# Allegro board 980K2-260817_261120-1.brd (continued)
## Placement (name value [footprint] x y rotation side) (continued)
NOREF#1107  -  []  201.84 295.2 0 top
NOREF#1108  -  []  88.14 151.13 90 top
NOREF#1109  -  []  194.33 267.37 90 top
NOREF#1110  -  []  237.18 236.17 90 top
NOREF#1111  -  []  243.97 210.55 90 top
NOREF#1112  -  []  204.95 264.23 90 top
NOREF#1113  -  []  230.6 233.69 90 top
NOREF#1114  -  []  281.75 206.13 0 top
NOREF#1115  -  []  186.16 253.35 0 top
NOREF#1116  -  []  214.09 207.27 90 top
NOREF#1117  -  []  283.84 200.97 90 top
NOREF#1118  -  []  266.83 251.93 0 top
NOREF#1119  -  []  275.92 255.7 90 top
NOREF#1120  -  []  276.81 172.54 0 top
NOREF#1121  -  []  236.81 172.54 0 top
NOREF#1122  -  []  149.84 213.7 0 top
NOREF#1123  -  []  196.7 257.85 90 top
NOREF#1124  -  []  152.25 282.59 0 top
NOREF#1125  -  []  242.57 231.95 0 top
NOREF#1126  -  []  233.56 233.37 90 top
NOREF#1127  -  []  262.81 186.81 0 top
NOREF#1128  -  []  187.99 238.35 0 top
NOREF#1129  -  []  147.43 224.11 0 top
NOREF#1130  -  []  265.61 197.6 0 top
NOREF#1131  -  []  149.72 221.62 0 top
NOREF#1132  -  []  228.95 266.89 0 top
NOREF#1133  -  []  168.42 265.58 0 top
NOREF#1134  -  []  142.03 289.03 90 top
NOREF#1135  -  []  262.87 273.02 0 top
NOREF#1136  -  []  187.3 286.19 0 top
NOREF#1137  -  []  168.42 205.58 0 top
NOREF#1138  -  []  279.22 239.57 90 top
NOREF#1139  -  []  119.48 456.29 0 top
NOREF#1140  -  []  188.81 195.7 90 top
NOREF#1141  -  []  241.75 266.13 0 top
NOREF#1142  -  []  89.74 155.92 90 top
NOREF#1143  -  []  233.98 238.07 0 top
NOREF#1144  -  []  277.74 226.35 90 top
NOREF#1145  -  []  248.54 260.64 90 top
NOREF#1146  -  []  166.32 214.76 0 top
NOREF#1147  -  []  176.98 265.11 90 top
NOREF#1148  -  []  199.4 202.09 0 top
NOREF#1149  -  []  222.6 82.65 0 top
NOREF#1150  -  []  211.05 185.49 90 top
NOREF#1151  -  []  141.55 205.11 90 top
NOREF#1152  -  []  239.27 265.58 0 top
NOREF#1153  -  []  237.5 185.31 90 top
NOREF#1154  -  []  149.78 228.3 0 top
NOREF#1155  -  []  187.8 209.99 0 top
NOREF#1156  -  []  149.24 185.31 90 top
NOREF#1157  -  []  243.84 208.62 0 top
NOREF#1158  -  []  283.97 270.55 90 top
NOREF#1159  -  []  156.45 247.71 0 top
NOREF#1160  -  []  187.9 265.84 90 top
NOREF#1161  -  []  133.78 207.01 0 top
NOREF#1162  -  []  272.25 212.18 90 top
NOREF#1163  -  []  270.41 168.7 90 top
NOREF#1164  -  []  279.4 272 0 top
NOREF#1165  -  []  283.84 214.21 0 top
NOREF#1166  -  []  149.56 259.27 90 top
NOREF#1167  -  []  228.99 240.62 0 top
NOREF#1168  -  []  230.77 219.22 90 top
NOREF#1169  -  []  149.84 224.11 90 top
NOREF#1170  -  []  129.05 292.28 0 top
NOREF#1171  -  []  241.75 214.76 0 top
NOREF#1172  -  []  239.65 212.56 0 top
NOREF#1173  -  []  215.65 184.35 0 top
NOREF#1174  -  []  248.54 205.9 0 top
NOREF#1175  -  []  266.96 196.43 90 top
NOREF#1176  -  []  258.95 204.09 0 top
NOREF#1177  -  []  156.57 245.63 90 top
NOREF#1178  -  []  254.51 203.76 0 top
NOREF#1179  -  []  207.95 286.12 90 top
NOREF#1180  -  []  153.6 216.55 0 top
NOREF#1181  -  []  123.91 295.42 90 top
NOREF#1182  -  []  220.95 208.91 90 top
NOREF#1183  -  []  279.22 179.57 90 top
NOREF#1184  -  []  293.02 392.33 90 top
NOREF#1185  -  []  268.32 193.35 0 top
NOREF#1186  -  []  155.17 272.17 90 top
NOREF#1187  -  []  192.25 282.59 90 top
NOREF#1188  -  []  271.71 171.3 0 top
NOREF#1189  -  []  187.43 224.11 90 top
NOREF#1190  -  []  193.95 196.75 0 top
NOREF#1191  -  []  279.72 219.22 90 top
NOREF#1192  -  []  209.52 260.42 90 top
NOREF#1193  -  []  263.49 197.85 90 top
NOREF#1194  -  []  228.32 182.05 0 top
NOREF#1195  -  []  157.37 191.6 90 top
NOREF#1196  -  []  237.04 244.35 0 top
NOREF#1197  -  []  249.05 292.28 0 top
NOREF#1198  -  []  155.17 276.75 0 top
NOREF#1199  -  []  147.43 218.27 90 top
NOREF#1200  -  []  166.32 274.76 0 top
NOREF#1201  -  []  144.04 256.75 0 top
NOREF#1202  -  []  156.7 241.72 90 top
NOREF#1203  -  []  228.32 242.05 0 top
NOREF#1204  -  []  272.13 284.66 0 top
NOREF#1205  -  []  229.84 273.7 0 top
NOREF#1206  -  []  214.09 264.23 90 top
NOREF#1207  -  []  158.64 233.37 90 top
NOREF#1208  -  []  246.32 272.22 0 top
NOREF#1209  -  []  279.65 272.56 0 top
NOREF#1210  -  []  279.27 274.21 0 top
NOREF#1211  -  []  135.02 208.14 90 top
NOREF#1212  -  []  197.71 233.69 90 top
NOREF#1213  -  []  239.27 274.21 0 top
NOREF#1214  -  []  180.83 261.22 90 top
NOREF#1215  -  []  151.19 218.07 0 top
NOREF#1216  -  []  199.27 274.21 0 top
NOREF#1217  -  []  279.22 190.88 90 top
NOREF#1218  -  []  243.84 214.21 0 top
NOREF#1219  -  []  229.72 221.62 0 top
NOREF#1220  -  []  214.43 232.23 0 top
NOREF#1221  -  []  178.35 207.01 0 top
NOREF#1222  -  []  94.87 102.74 90 top
NOREF#1223  -  []  147.77 248.11 90 top
NOREF#1224  -  []  122.85 281.02 0 top
NOREF#1225  -  []  122.2 178.35 0 top
NOREF#1226  -  []  190.56 197.6 0 top
NOREF#1227  -  []  192.13 284.66 0 top
NOREF#1228  -  []  236.57 193.35 0 top
NOREF#1229  -  []  271.11 198.18 0 top
NOREF#1230  -  []  187.03 231.4 0 top
NOREF#1231  -  []  255.84 262.57 90 top
NOREF#1232  -  []  270.77 273.37 90 top
NOREF#1233  -  []  260.95 264.09 90 top
NOREF#1234  -  []  199.06 238.07 0 top
NOREF#1235  -  []  229.84 219.54 90 top
NOREF#1236  -  []  277.71 173.69 0 top
NOREF#1237  -  []  176.63 232.23 0 top
NOREF#1238  -  []  221.55 202.57 90 top
NOREF#1239  -  []  276.84 167.33 0 top
NOREF#1240  -  []  204.95 204.23 90 top
NOREF#1241  -  []  150.56 247.68 0 top
NOREF#1242  -  []  150.48 235.77 0 top
NOREF#1243  -  []  231.98 280.75 90 top
NOREF#1244  -  []  182.03 289.03 90 top
NOREF#1245  -  []  206.32 206.13 0 top
NOREF#1246  -  []  175.65 184.35 0 top
NOREF#1247  -  []  148.32 185.63 90 top
NOREF#1248  -  []  226.16 272.17 90 top
NOREF#1249  -  []  139.08 208.59 0 top
NOREF#1250  -  []  148.44 197.85 90 top
NOREF#1251  -  []  157.92 247.68 90 top
NOREF#1252  -  []  283.84 260.97 90 top
NOREF#1253  -  []  176.38 204.09 90 top
NOREF#1254  -  []  203.04 236.5 90 top
NOREF#1255  -  []  178.35 269.04 0 top
NOREF#1256  -  []  276.45 247.71 0 top
NOREF#1257  -  []  220.63 392.33 90 top
NOREF#1258  -  []  124.61 294.89 90 top
NOREF#1259  -  []  161.75 262.32 0 top
NOREF#1260  -  []  283.97 212 0 top
NOREF#1261  -  []  199.72 274.65 90 top
NOREF#1262  -  []  258.35 264.47 0 top
NOREF#1263  -  []  251.65 233.3 90 top
NOREF#1264  -  []  274.07 191.6 90 top
NOREF#1265  -  []  260.83 201.22 90 top
NOREF#1266  -  []  279.4 212 0 top
NOREF#1267  -  []  277.71 233.69 0 top
NOREF#1268  -  []  80.49 135.25 0 top
NOREF#1269  -  []  283.84 261.77 0 top
NOREF#1270  -  []  228.44 197.85 90 top
NOREF#1271  -  []  272.25 272.17 90 top
NOREF#1272  -  []  222.87 226.99 0 top
NOREF#1273  -  []  260.83 263.76 90 top
NOREF#1274  -  []  254.04 210.63 90 top
NOREF#1275  -  []  131.05 289.49 0 top
NOREF#1276  -  []  211.25 184.35 0 top
NOREF#1277  -  []  190.77 213.37 90 top
NOREF#1278  -  []  235.05 274.25 0 top
NOREF#1279  -  []  177.29 247.78 0 top
NOREF#1280  -  []  176.98 205.11 90 top
NOREF#1281  -  []  257.25 176.5 90 top
NOREF#1282  -  []  235.17 276.75 90 top
NOREF#1283  -  []  248.54 200.64 90 top
NOREF#1284  -  []  239.27 214.21 0 top
NOREF#1285  -  []  189.84 219.54 0 top
NOREF#1286  -  []  273.83 232.21 90 top
NOREF#1287  -  []  142.88 226.99 0 top
NOREF#1288  -  []  152.13 284.66 0 top
NOREF#1289  -  []  232.11 171.4 0 top
NOREF#1290  -  []  194.39 216.17 90 top
NOREF#1291  -  []  139.08 268.59 0 top
NOREF#1292  -  []  153.27 198.18 0 top
NOREF#1293  -  []  156.7 257.85 90 top
NOREF#1294  -  []  238.99 19.69 90 top
NOREF#1295  -  []  227.77 197.6 0 top
NOREF#1296  -  []  268.89 392.33 90 top
NOREF#1297  -  []  151.76 167.33 0 top
NOREF#1298  -  []  208.54 268.95 0 top
NOREF#1299  -  []  150.6 173.69 0 top
NOREF#1300  -  []  201.75 272.22 0 top
NOREF#1301  -  []  188.44 197.85 90 top
NOREF#1302  -  []  227.8 269.99 0 top
NOREF#1303  -  []  196.38 241.15 90 top
NOREF#1304  -  []  290.89 269.17 0 top
NOREF#1305  -  []  133.62 289.09 90 top
NOREF#1306  -  []  151.91 256.43 90 top
NOREF#1307  -  []  302.26 14.59 90 top
NOREF#1308  -  []  271.19 223.92 0 top
NOREF#1309  -  []  268.44 193.03 90 top
NOREF#1310  -  []  268.44 253.03 90 top
NOREF#1311  -  []  179.08 268.59 0 top
NOREF#1312  -  []  199.65 212.56 0 top
NOREF#1313  -  []  159.27 210.87 90 top
NOREF#1314  -  []  150.6 233.69 90 top
NOREF#1315  -  []  156.57 258.18 0 top
NOREF#1316  -  []  218.35 207.01 0 top
NOREF#1317  -  []  218.95 266.12 0 top
NOREF#1318  -  []  208.45 295.2 0 top
NOREF#1319  -  []  275.17 212.18 0 top
NOREF#1320  -  []  230.97 255.7 90 top
NOREF#1321  -  []  188.35 277.95 90 top
NOREF#1322  -  []  180.59 244.98 90 top
NOREF#1323  -  []  243.97 264.45 90 top
NOREF#1324  -  []  267.3 280.35 0 top
NOREF#1325  -  []  149.84 273.7 90 top
NOREF#1326  -  []  235.05 278.82 0 top
NOREF#1327  -  []  195.68 233.69 90 top
NOREF#1328  -  []  163.4 236.38 0 top
NOREF#1329  -  []  196.57 198.18 0 top
NOREF#1330  -  []  124.55 148.49 90 top
NOREF#1331  -  []  293.99 17.15 0 top
NOREF#1332  -  []  196.1 276.42 90 top
NOREF#1333  -  []  151.71 231.3 0 top
NOREF#1334  -  []  197.59 175.77 0 top
NOREF#1335  -  []  227.8 264.99 90 top
NOREF#1336  -  []  272.13 220.09 0 top
NOREF#1337  -  []  267.03 171.4 0 top
NOREF#1338  -  []  179.72 213.6 90 top
NOREF#1339  -  []  202.57 231.95 0 top
NOREF#1340  -  []  270.41 228.7 90 top
NOREF#1341  -  []  231.79 256.75 0 top
NOREF#1342  -  []  228.81 195.7 90 top
NOREF#1343  -  []  269.12 196.43 90 top
NOREF#1344  -  []  286.32 274.76 0 top
NOREF#1345  -  []  190.48 175.77 0 top
NOREF#1346  -  []  242.57 291.95 0 top
NOREF#1347  -  []  206.32 212.22 0 top
NOREF#1348  -  []  221.55 267.14 90 top
NOREF#1349  -  []  133.1 237.5 0 top
NOREF#1350  -  []  129.05 232.28 0 top
NOREF#1351  -  []  196.57 253.35 0 top
NOREF#1352  -  []  157.74 226.35 90 top
NOREF#1353  -  []  153.95 196.75 0 top
NOREF#1354  -  []  263.49 187.06 90 top
NOREF#1355  -  []  268.32 245.63 0 top
NOREF#1356  -  []  188.81 255.7 90 top
NOREF#1357  -  []  157.18 236.17 90 top
NOREF#1358  -  []  186.16 226.14 90 top
NOREF#1359  -  []  253.62 229.09 90 top
NOREF#1360  -  []  281.12 188.11 90 top
NOREF#1361  -  []  146.17 226.14 90 top
NOREF#1362  -  []  136.38 264.09 90 top
NOREF#1363  -  []  197.25 240.62 0 top
NOREF#1364  -  []  262.81 197.6 0 top
NOREF#1365  -  []  95.35 456.29 90 top
NOREF#1366  -  []  276.38 241.15 90 top
NOREF#1367  -  []  157.37 180.3 90 top
NOREF#1368  -  []  283.97 213.09 90 top
NOREF#1369  -  []  272.63 233.69 0 top
NOREF#1370  -  []  261.55 207.14 90 top
NOREF#1371  -  []  276.02 241.47 0 top
NOREF#1372  -  []  180.83 201.22 90 top
NOREF#1373  -  []  187.8 269.99 0 top
NOREF#1374  -  []  159.27 273.41 90 top
NOREF#1375  -  []  164.95 212.86 90 top
NOREF#1376  -  []  155.05 278.82 0 top
NOREF#1377  -  []  136.83 227.03 0 top
NOREF#1378  -  []  270.6 233.69 90 top
NOREF#1379  -  []  174.07 210.89 90 top
NOREF#1380  -  []  221.85 306.46 0 top
NOREF#1381  -  []  178.95 204.09 0 top
NOREF#1382  -  []  203.97 213.09 90 top
NOREF#1383  -  []  147.43 284.11 90 top
NOREF#1384  -  []  289.52 270.32 90 top
NOREF#1385  -  []  174.09 264.23 90 top
NOREF#1386  -  []  163.97 265.9 0 top
NOREF#1387  -  []  168.54 204.45 90 top
NOREF#1388  -  []  227.43 218.27 0 top
NOREF#1389  -  []  172.87 227.4 90 top
NOREF#1390  -  []  275.05 218.82 0 top
NOREF#1391  -  []  173.65 239.15 0 top
NOREF#1392  -  []  206.32 202.32 0 top
NOREF#1393  -  []  203.84 200.97 90 top
NOREF#1394  -  []  231.18 179.15 0 top
NOREF#1395  -  []  162.85 237.22 0 top
NOREF#1396  -  []  273.6 216.55 0 top
NOREF#1397  -  []  157.04 184.35 0 top
NOREF#1398  -  []  151.7 288.26 0 top
NOREF#1399  -  []  196.02 257.6 0 top
NOREF#1400  -  []  156.54 167 0 top
NOREF#1401  -  []  196.7 197.85 90 top
NOREF#1402  -  []  191.19 288.49 0 top
NOREF#1403  -  []  221.59 234.15 0 top
NOREF#1404  -  []  159.22 179.57 90 top
NOREF#1405  -  []  239.4 274.54 0 top
NOREF#1406  -  []  226.01 190.88 90 top
NOREF#1407  -  []  276.33 167.9 90 top
NOREF#1408  -  []  209.52 207.27 90 top
NOREF#1409  -  []  279.27 207.82 90 top
NOREF#1410  -  []  266.16 193.35 0 top
NOREF#1411  -  []  153.95 256.75 0 top
NOREF#1412  -  []  277.37 180.3 90 top
NOREF#1413  -  []  188.32 185.63 0 top
NOREF#1414  -  []  222.81 186.81 0 top
NOREF#1415  -  []  188.99 240.62 0 top
NOREF#1416  -  []  248.45 235.2 0 top
NOREF#1417  -  []  179.08 203.76 0 top
NOREF#1418  -  []  265.41 286.99 90 top
NOREF#1419  -  []  279.4 270.55 90 top
NOREF#1420  -  []  138.95 201.55 0 top
NOREF#1421  -  []  235.27 458.49 0 top
NOREF#1422  -  []  169.52 200.42 90 top
NOREF#1423  -  []  141.6 234.15 0 top
NOREF#1424  -  []  156.02 251.31 0 top
NOREF#1425  -  []  288.54 260.64 90 top
NOREF#1426  -  []  157.25 256.75 0 top
NOREF#1427  -  []  219.55 240.49 90 top
NOREF#1428  -  []  268.32 253.35 0 top
NOREF#1429  -  []  149.84 219.54 0 top
NOREF#1430  -  []  273.18 217.69 90 top
NOREF#1431  -  []  231.73 172.54 0 top
NOREF#1432  -  []  209.52 200.42 90 top
NOREF#1433  -  []  192.11 231.4 0 top
NOREF#1434  -  []  213.62 289.09 90 top
NOREF#1435  -  []  203.4 296.38 0 top
NOREF#1436  -  []  190.41 228.7 90 top
NOREF#1437  -  []  251.05 292.28 90 top
NOREF#1438  -  []  193.39 257.85 90 top
NOREF#1439  -  []  88.16 144.87 0 top
NOREF#1440  -  []  204.95 270.32 90 top
NOREF#1441  -  []  168.54 208.95 0 top
NOREF#1442  -  []  186.01 184.91 90 top
NOREF#1443  -  []  197.25 180.62 0 top
NOREF#1444  -  []  203.97 270.55 90 top
NOREF#1445  -  []  131.05 292.28 90 top
NOREF#1446  -  []  140.83 265.79 90 top
NOREF#1447  -  []  178.35 271.84 0 top
NOREF#1448  -  []  268.99 196.75 0 top
NOREF#1449  -  []  207.04 239.09 0 top
NOREF#1450  -  []  135.15 260.67 0 top
NOREF#1451  -  []  153.03 172.1 0 top
NOREF#1452  -  []  148.95 266.89 0 top
NOREF#1453  -  []  147.05 209.24 0 top
NOREF#1454  -  []  148.44 253.03 90 top
NOREF#1455  -  []  224.04 185.96 0 top
NOREF#1456  -  []  168.54 207.5 90 top
NOREF#1457  -  []  194.78 176.5 90 top
NOREF#1458  -  []  228.78 288.49 0 top
NOREF#1459  -  []  181.94 389.27 90 top
NOREF#1460  -  []  146.01 190.88 90 top
NOREF#1461  -  []  190.98 184.35 0 top
NOREF#1462  -  []  221.03 267.69 90 top
NOREF#1463  -  []  186.96 191.6 90 top
NOREF#1464  -  []  197.04 244.35 0 top
NOREF#1465  -  []  164.95 204.23 90 top
NOREF#1466  -  []  268.99 256.75 0 top
NOREF#1467  -  []  192.63 173.69 0 top
NOREF#1468  -  []  239.27 207.82 90 top
NOREF#1469  -  []  200.23 236.17 90 top
NOREF#1470  -  []  233.27 258.18 0 top
NOREF#1471  -  []  133.45 244.35 0 top
NOREF#1472  -  []  245.04 293.3 90 top
NOREF#1473  -  []  243.84 201.77 0 top
NOREF#1474  -  []  143.49 253.03 90 top
NOREF#1475  -  []  229.12 240.3 90 top
NOREF#1476  -  []  219.72 213.6 90 top
NOREF#1477  -  []  220.83 261.22 90 top
NOREF#1478  -  []  163.04 176.5 90 top
NOREF#1479  -  []  248.94 281.73 0 top
NOREF#1480  -  []  227.77 252.78 0 top
NOREF#1481  -  []  273.26 456.29 0 top
NOREF#1482  -  []  176.74 456.29 0 top
NOREF#1483  -  []  198.11 172.1 0 top
NOREF#1484  -  []  234.39 226.59 90 top
NOREF#1485  -  []  270.98 244.35 0 top
NOREF#1486  -  []  185.61 197.6 0 top
NOREF#1487  -  []  283.97 272 0 top
NOREF#1488  -  []  125.38 226.23 0 top
NOREF#1489  -  []  276.84 227.33 0 top
NOREF#1490  -  []  181.85 306.46 0 top
NOREF#1491  -  []  255.65 244.35 0 top
NOREF#1492  -  []  268.35 283.79 90 top
NOREF#1493  -  []  226.7 297.01 90 top
NOREF#1494  -  []  183.89 185.24 90 top
NOREF#1495  -  []  258.95 208.91 0 top
NOREF#1496  -  []  258.95 266.12 0 top
NOREF#1497  -  []  269.55 248.99 90 top
NOREF#1498  -  []  268.95 206.89 0 top
NOREF#1499  -  []  199.4 273.09 90 top
NOREF#1500  -  []  231.91 256.43 90 top
NOREF#1501  -  []  197.71 232.86 0 top
NOREF#1502  -  []  275.17 272.17 0 top
NOREF#1503  -  []  271.98 226.59 90 top
NOREF#1504  -  []  172.64 204.47 0 top
NOREF#1505  -  []  260.95 208.91 90 top
NOREF#1506  -  []  289.52 200.42 90 top
NOREF#1507  -  []  180.83 268.59 90 top
NOREF#1508  -  []  232.25 282.59 0 top
NOREF#1509  -  []  158.11 172.1 0 top
NOREF#1510  -  []  192.25 212.18 90 top
NOREF#1511  -  []  190.6 173.69 90 top
NOREF#1512  -  []  163.97 202.09 0 top
NOREF#1513  -  []  261.85 232.5 0 top
NOREF#1514  -  []  273.76 195.7 90 top
NOREF#1515  -  []  204.95 207.27 90 top
NOREF#1516  -  []  95.35 396.29 0 top
NOREF#1517  -  []  144.71 252.5 90 top
NOREF#1518  -  []  281.44 184.35 0 top
NOREF#1519  -  []  171.25 184.35 0 top
NOREF#1520  -  []  183.49 257.85 90 top
NOREF#1521  -  []  155.15 176.17 90 top
NOREF#1522  -  []  278.45 14.59 90 top
NOREF#1523  -  []  229.84 279.54 0 top
NOREF#1524  -  []  192.66 166.36 90 top
NOREF#1525  -  []  249.05 232.28 0 top
NOREF#1526  -  []  193.39 193.03 90 top
NOREF#1527  -  []  232.25 212.18 90 top
NOREF#1528  -  []  241.41 167.9 90 top
NOREF#1529  -  []  149.29 285.22 0 top
NOREF#1530  -  []  189.84 224.11 0 top
NOREF#1531  -  []  179.08 208.59 0 top
NOREF#1532  -  []  211.65 233.3 90 top
NOREF#1533  -  []  148.99 196.75 0 top
NOREF#1534  -  []  123.4 236.38 0 top
NOREF#1535  -  []  258.35 211.84 0 top
NOREF#1536  -  []  154.63 274.65 90 top
NOREF#1537  -  []  261.55 202.57 90 top
NOREF#1538  -  []  150.77 283.79 90 top
NOREF#1539  -  []  195.17 216.75 0 top
NOREF#1540  -  []  152.11 171.4 0 top
NOREF#1541  -  []  243.84 270.87 90 top
NOREF#1542  -  []  149.55 318.49 0 top
NOREF#1543  -  []  237.18 176.17 90 top
NOREF#1544  -  []  193.18 222.26 90 top
NOREF#1545  -  []  239.4 265.9 0 top
NOREF#1546  -  []  195.17 216.75 90 top
NOREF#1547  -  []  197.5 245.31 90 top
NOREF#1548  -  []  224.16 256.43 90 top
NOREF#1549  -  []  157.03 238.07 0 top
NOREF#1550  -  []  161.75 209.17 0 top
NOREF#1551  -  []  271.53 233.37 90 top
NOREF#1552  -  []  163.84 208.62 0 top
NOREF#1553  -  []  195.68 173.69 90 top
NOREF#1554  -  []  193.39 253.03 90 top
NOREF#1555  -  []  236.7 253.03 90 top
NOREF#1556  -  []  238.64 173.37 90 top
NOREF#1557  -  []  180.95 201.55 90 top
NOREF#1558  -  []  159.22 190.88 90 top
NOREF#1559  -  []  269.84 213.7 0 top
NOREF#1560  -  []  122.57 231.95 0 top
NOREF#1561  -  []  209.17 291.95 0 top
NOREF#1562  -  []  182.81 192.78 0 top
NOREF#1563  -  []  203.84 260.97 90 top
NOREF#1564  -  []  151.79 256.75 0 top
NOREF#1565  -  []  149.84 284.11 0 top
NOREF#1566  -  []  177.25 176.5 90 top
NOREF#1567  -  []  153.98 238.07 0 top
NOREF#1568  -  []  275.05 278.82 0 top
NOREF#1569  -  []  159.24 184.35 0 top
NOREF#1570  -  []  237.5 245.31 90 top
NOREF#1571  -  []  157.59 235.77 0 top
NOREF#1572  -  []  174.04 270.63 90 top
NOREF#1573  -  []  162.2 178.35 0 top
NOREF#1574  -  []  188.19 187.71 0 top
NOREF#1575  -  []  147.45 269.24 0 top
NOREF#1576  -  []  271.53 173.37 90 top
NOREF#1577  -  []  169.52 212.86 90 top
NOREF#1578  -  []  199.4 212 0 top
NOREF#1579  -  []  270.48 175.77 0 top
NOREF#1580  -  []  269.84 273.7 0 top
NOREF#1581  -  []  272.72 192.78 0 top
NOREF#1582  -  []  172.64 264.47 0 top
NOREF#1583  -  []  167.95 286.12 90 top
NOREF#1584  -  []  272.25 278.02 0 top
NOREF#1585  -  []  106.68 128.02 0 top
NOREF#1586  -  []  178.83 292.23 0 top
NOREF#1587  -  []  264.16 256.43 90 top
NOREF#1588  -  []  143.36 247.38 0 top
NOREF#1589  -  []  220.95 201.55 90 top
NOREF#1590  -  []  192.25 272.17 90 top
NOREF#1591  -  []  144.04 251.93 0 top
NOREF#1592  -  []  229.72 215.77 0 top
NOREF#1593  -  []  268.35 277.95 90 top
NOREF#1594  -  []  253.64 299.09 0 top
NOREF#1595  -  []  137.29 187.78 0 top
NOREF#1596  -  []  273.03 232.1 0 top
NOREF#1597  -  []  229.67 250.01 0 top
NOREF#1598  -  []  209.52 267.27 90 top
NOREF#1599  -  []  179.73 238.35 0 top
NOREF#1600  -  []  194.07 256.43 90 top
NOREF#1601  -  []  221.55 269.94 90 top
NOREF#1602  -  []  130.92 291.95 90 top
NOREF#1603  -  []  199.27 264.78 90 top
NOREF#1604  -  []  259.55 240.49 90 top
NOREF#1605  -  []  182.81 197.6 0 top
NOREF#1606  -  []  147.8 205.39 90 top
NOREF#1607  -  []  283.84 271.67 0 top
NOREF#1608  -  []  227.43 278.27 90 top
NOREF#1609  -  []  237.59 235.77 0 top
NOREF#1610  -  []  258.85 241.15 90 top
NOREF#1611  -  []  157.37 256.43 90 top
NOREF#1612  -  []  233.6 226.96 0 top
NOREF#1613  -  []  171.22 294.24 90 top
NOREF#1614  -  []  144.71 247.68 90 top
NOREF#1615  -  []  141.6 248.12 0 top
NOREF#1616  -  []  268.78 228.49 0 top
NOREF#1617  -  []  214.09 267.27 90 top
NOREF#1618  -  []  204.95 267.27 90 top
NOREF#1619  -  []  190.6 233.69 90 top
NOREF#1620  -  []  267.43 284.11 90 top
NOREF#1621  -  []  135.82 266.44 0 top
NOREF#1622  -  []  183.49 197.85 90 top
NOREF#1623  -  []  174.34 82.65 0 top
NOREF#1624  -  []  244.44 232.28 90 top
NOREF#1625  -  []  191.53 233.37 90 top
NOREF#1626  -  []  275.15 176.17 90 top
NOREF#1627  -  []  235.17 221.32 90 top
NOREF#1628  -  []  196.81 172.54 0 top
NOREF#1629  -  []  182.87 213.02 0 top
NOREF#1630  -  []  262.03 229.03 90 top
NOREF#1631  -  []  265.09 257.49 90 top
NOREF#1632  -  []  254.09 264.23 90 top
NOREF#1633  -  []  150.97 195.7 90 top
NOREF#1634  -  []  279.06 178.07 0 top
NOREF#1635  -  []  264.04 196.75 0 top
NOREF#1636  -  []  137.28 272.5 0 top
NOREF#1637  -  []  249.52 272.86 90 top
NOREF#1638  -  []  196.61 233.37 90 top
NOREF#1639  -  []  135.43 276.18 0 top
NOREF#1640  -  []  300.14 320.9 0 top
NOREF#1641  -  []  161.75 206.13 0 top
NOREF#1642  -  []  159.27 214.21 0 top
NOREF#1643  -  []  289.52 210.32 90 top
NOREF#1644  -  []  288.54 207.5 90 top
NOREF#1645  -  []  157.71 172.86 0 top
NOREF#1646  -  []  174.43 292.23 0 top
NOREF#1647  -  []  163.97 260.64 90 top
NOREF#1648  -  []  250.02 214.45 0 top
NOREF#1649  -  []  283.97 267.5 90 top
NOREF#1650  -  []  106.58 18.69 90 top
NOREF#1651  -  []  151.24 197.85 90 top
NOREF#1652  -  []  190.77 223.79 90 top
NOREF#1653  -  []  125.08 17.15 90 top
NOREF#1654  -  []  269.84 279.54 90 top
NOREF#1655  -  []  189.72 221.62 0 top
NOREF#1656  -  []  274.33 264.33 90 top
NOREF#1657  -  []  192.72 197.6 0 top
NOREF#1658  -  []  149.55 248.99 90 top
NOREF#1659  -  []  194.07 196.43 90 top
NOREF#1660  -  []  286.32 209.17 0 top
NOREF#1661  -  []  84.45 359.42 0 top
NOREF#1662  -  []  279.22 250.88 90 top
NOREF#1663  -  []  168.94 281.73 0 top
NOREF#1664  -  []  274.33 267.37 90 top
NOREF#1665  -  []  210.89 262.32 0 top
NOREF#1666  -  []  189.84 224.11 90 top
NOREF#1667  -  []  256.55 280.49 0 top
NOREF#1668  -  []  262.81 192.78 0 top
NOREF#1669  -  []  154.63 286.99 0 top
NOREF#1670  -  []  279.24 184.35 0 top
NOREF#1671  -  []  176.38 264.09 90 top
NOREF#1672  -  []  148.32 185.63 0 top
NOREF#1673  -  []  279.4 265.9 0 top
NOREF#1674  -  []  228.32 258.18 0 top
NOREF#1675  -  []  277.37 251.6 90 top
NOREF#1676  -  []  288.54 264.45 90 top
NOREF#1677  -  []  152.87 188.11 90 top
NOREF#1678  -  []  235.56 235.77 0 top
NOREF#1679  -  []  227.43 218.27 90 top
NOREF#1680  -  []  256.38 264.09 90 top
NOREF#1681  -  []  273.18 211.85 90 top
NOREF#1682  -  []  148.35 283.79 90 top
NOREF#1683  -  []  267.99 178.35 0 top
NOREF#1684  -  []  235.17 272.17 0 top
NOREF#1685  -  []  143.36 187.38 0 top
NOREF#1686  -  []  144.04 196.75 0 top
NOREF#1687  -  []  277.37 196.43 90 top
NOREF#1688  -  []  239.4 213.09 90 top
NOREF#1689  -  []  188.81 190.88 90 top
NOREF#1690  -  []  140.04 265.53 90 top
NOREF#1691  -  []  276.57 193.35 0 top
NOREF#1692  -  []  195.05 283.39 0 top
NOREF#1693  -  []  266.16 286.14 90 top
NOREF#1694  -  []  218.97 211.91 90 top
NOREF#1695  -  []  243.84 264.78 90 top
NOREF#1696  -  []  264.16 196.43 90 top
NOREF#1697  -  []  172.55 250.49 90 top
NOREF#1698  -  []  227.05 209.24 0 top
NOREF#1699  -  []  191.24 193.03 90 top
NOREF#1700  -  []  148.99 251.93 0 top
NOREF#1701  -  []  231.79 251.93 0 top
NOREF#1702  -  []  164.95 260.42 90 top
NOREF#1703  -  []  171.05 232.28 90 top
NOREF#1704  -  []  226.28 197.85 90 top
NOREF#1705  -  []  156.1 276.42 90 top
NOREF#1706  -  []  140.83 261.22 90 top
NOREF#1707  -  []  267.77 197.6 0 top
NOREF#1708  -  []  191.19 223.92 0 top
NOREF#1709  -  []  153.6 226.96 0 top
NOREF#1710  -  []  270.77 279.22 90 top
NOREF#1711  -  []  166.32 262.32 0 top
NOREF#1712  -  []  284.64 181.15 90 top
NOREF#1713  -  []  226.96 196.43 90 top
NOREF#1714  -  []  277.25 180.62 0 top
NOREF#1715  -  []  196.8 214.65 90 top
NOREF#1716  -  []  275.17 221.32 90 top
NOREF#1717  -  []  184.04 185.96 0 top
NOREF#1718  -  []  138.75 457.2 0 top
NOREF#1719  -  []  187.8 204.99 90 top
NOREF#1720  -  []  191.53 173.37 90 top
NOREF#1721  -  []  233.27 253.35 0 top
NOREF#1722  -  []  176.63 292.23 0 top
NOREF#1723  -  []  267.99 238.35 0 top
NOREF#1724  -  []  277.71 173.69 90 top
NOREF#1725  -  []  224.16 191.6 90 top
NOREF#1726  -  []  188.78 244.35 0 top
NOREF#1727  -  []  210.89 202.32 0 top
NOREF#1728  -  []  203.97 267.5 90 top
NOREF#1729  -  []  203.84 264.78 90 top
NOREF#1730  -  []  273.94 191.93 0 top
NOREF#1731  -  []  260.59 244.98 90 top
NOREF#1732  -  []  283.84 211.67 0 top
NOREF#1733  -  []  284.64 241.15 90 top
NOREF#1734  -  []  189.12 180.3 90 top
NOREF#1735  -  []  156.57 198.18 0 top
NOREF#1736  -  []  149.72 215.77 0 top
NOREF#1737  -  []  232.87 248.11 90 top
NOREF#1738  -  []  241.84 295.2 0 top
NOREF#1739  -  []  168.54 202.09 0 top
NOREF#1740  -  []  199.4 200.64 90 top
NOREF#1741  -  []  140.83 205.79 90 top
NOREF#1742  -  []  288.54 267.5 90 top
NOREF#1743  -  []  288.42 268.62 0 top
NOREF#1744  -  []  227.43 284.11 90 top
NOREF#1745  -  []  215.11 201.22 90 top
NOREF#1746  -  []  163.4 296.38 0 top
NOREF#1747  -  []  219.08 208.59 0 top
NOREF#1748  -  []  261.85 246.47 0 top
NOREF#1749  -  []  161.75 272.22 0 top
NOREF#1750  -  []  214.43 292.23 0 top
NOREF#1751  -  []  212.55 190.49 90 top
NOREF#1752  -  []  148.32 198.18 0 top
NOREF#1753  -  []  204.61 234.24 90 top
NOREF#1754  -  []  146.16 193.35 0 top
NOREF#1755  -  []  256.26 203.76 90 top
NOREF#1756  -  []  284.95 264.23 90 top
NOREF#1757  -  []  235.68 233.69 0 top
NOREF#1758  -  []  222.03 229.03 90 top
NOREF#1759  -  []  168.42 264.78 90 top
NOREF#1760  -  []  272.72 252.78 0 top
NOREF#1761  -  []  231.19 283.92 0 top
NOREF#1762  -  []  138.74 83.81 0 top
NOREF#1763  -  []  209.55 237.49 0 top
NOREF#1764  -  []  234.07 191.6 90 top
NOREF#1765  -  []  149.84 224.11 0 top
NOREF#1766  -  []  225.41 286.99 90 top
NOREF#1767  -  []  251.36 18.69 90 top
NOREF#1768  -  []  231.18 239.15 0 top
NOREF#1769  -  []  178.35 267.01 0 top
NOREF#1770  -  []  227.43 224.11 0 top
NOREF#1771  -  []  131.26 244.35 0 top
NOREF#1772  -  []  223.49 257.85 90 top
NOREF#1773  -  []  196.02 241.47 0 top
NOREF#1774  -  []  147.77 247.68 0 top
NOREF#1775  -  []  275.92 250.88 90 top
NOREF#1776  -  []  189.55 188.99 90 top
NOREF#1777  -  []  269.84 219.54 0 top
NOREF#1778  -  []  244.61 294.89 90 top
NOREF#1779  -  []  270.88 228.6 90 top
NOREF#1780  -  []  153.39 193.03 90 top
NOREF#1781  -  []  272.25 278.02 90 top
NOREF#1782  -  []  272.25 282.59 90 top
NOREF#1783  -  []  226.96 191.6 90 top
NOREF#1784  -  []  219.08 203.76 0 top
NOREF#1785  -  []  141.55 209.94 90 top
NOREF#1786  -  []  203.84 210.87 90 top
NOREF#1787  -  []  232.13 214.25 0 top
NOREF#1788  -  []  147.77 192.78 0 top
NOREF#1789  -  []  186.83 251.93 0 top
NOREF#1790  -  []  226.16 253.35 0 top
NOREF#1791  -  []  241.75 202.32 0 top
NOREF#1792  -  []  130.02 274.45 0 top
NOREF#1793  -  []  187.8 265.39 90 top
NOREF#1794  -  []  195.58 202.67 90 top
NOREF#1795  -  []  274.39 276.17 90 top
NOREF#1796  -  []  211.05 245.49 90 top
NOREF#1797  -  []  135.84 202.57 90 top
NOREF#1798  -  []  229.84 224.11 0 top
NOREF#1799  -  []  227.05 269.24 0 top
NOREF#1800  -  []  260.83 265.79 90 top
NOREF#1801  -  []  284.95 260.42 90 top
NOREF#1802  -  []  203.97 204.45 90 top
NOREF#1803  -  []  280.23 176.17 90 top
NOREF#1804  -  []  258.35 267.01 0 top
NOREF#1805  -  []  234.33 204.33 90 top
NOREF#1806  -  []  210.89 266.13 0 top
NOREF#1807  -  []  187.8 205.39 90 top
NOREF#1808  -  []  227.77 181.47 0 top
NOREF#1809  -  []  178.95 261.55 0 top
NOREF#1810  -  []  148.44 257.85 90 top
NOREF#1811  -  []  242.2 178.35 0 top
NOREF#1812  -  []  258.35 209.04 0 top
NOREF#1813  -  []  187.43 224.11 0 top
NOREF#1814  -  []  139.08 265.79 0 top
NOREF#1815  -  []  228.99 196.75 0 top
NOREF#1816  -  []  155.96 228.6 90 top
NOREF#1817  -  []  260.83 203.76 90 top
NOREF#1818  -  []  268.78 244.35 0 top
NOREF#1819  -  []  236.52 216.55 0 top
NOREF#1820  -  []  279.27 213.41 90 top
NOREF#1821  -  []  190.97 195.7 90 top
NOREF#1822  -  []  236.02 257.6 0 top
NOREF#1823  -  []  138.95 204.09 0 top
NOREF#1824  -  []  148.32 193.35 0 top
NOREF#1825  -  []  190.41 168.7 90 top
NOREF#1826  -  []  175.02 268.14 90 top
NOREF#1827  -  []  152.25 218.02 90 top
NOREF#1828  -  []  276.45 187.71 0 top
NOREF#1829  -  []  324.88 21.69 90 top
NOREF#1830  -  []  268.99 251.93 0 top
NOREF#1831  -  []  280.23 236.17 90 top
NOREF#1832  -  []  279.4 204.45 90 top
NOREF#1833  -  []  242.26 176.17 90 top
NOREF#1834  -  []  231.11 258.18 0 top
NOREF#1835  -  []  203.04 176.5 90 top
NOREF#1836  -  []  197.71 233.69 0 top
NOREF#1837  -  []  236.8 285.06 90 top
NOREF#1838  -  []  141.03 207.69 90 top
NOREF#1839  -  []  273.94 256.75 0 top
NOREF#1840  -  []  231.11 253.35 0 top
NOREF#1841  -  []  245.04 233.3 90 top
NOREF#1842  -  []  244.61 234.24 90 top
NOREF#1843  -  []  232.72 252.78 0 top
NOREF#1844  -  []  269.24 245.31 90 top
NOREF#1845  -  []  208.42 265.58 0 top
NOREF#1846  -  []  192.25 218.02 90 top
NOREF#1847  -  []  197.18 176.17 90 top
NOREF#1848  -  []  240.13 396.29 0 top
NOREF#1849  -  []  188.44 253.03 90 top
NOREF#1850  -  []  156.57 182.05 0 top
NOREF#1851  -  []  165.38 226.23 0 top
NOREF#1852  -  []  269.84 224.11 0 top
NOREF#1853  -  []  236.1 271.85 90 top
NOREF#1854  -  []  248.54 207.5 90 top
NOREF#1855  -  []  149.78 228.3 0 top
NOREF#1856  -  []  271.11 200.17 90 top
NOREF#1857  -  []  254.04 270.63 90 top
NOREF#1858  -  []  100.95 17.15 90 top
NOREF#1859  -  []  237.25 251.93 0 top
NOREF#1860  -  []  157.71 232.86 0 top
NOREF#1861  -  []  161.75 202.32 0 top
NOREF#1862  -  []  142.88 273.02 0 top
NOREF#1863  -  []  284.95 200.42 90 top
NOREF#1864  -  []  256.26 263.76 90 top
NOREF#1865  -  []  156.02 197.6 0 top
NOREF#1866  -  []  276.52 216.55 0 top
NOREF#1867  -  []  227.3 226.19 0 top
NOREF#1868  -  []  266.69 237.02 90 top
NOREF#1869  -  []  233.76 195.7 90 top
NOREF#1870  -  []  203.84 265.58 0 top
NOREF#1871  -  []  123.4 281.8 0 top
NOREF#1872  -  []  216.83 227.03 0 top
NOREF#1873  -  []  159.4 265.9 0 top
NOREF#1874  -  []  88.14 130.81 90 top
NOREF#1875  -  []  158.91 172.21 90 top
NOREF#1876  -  []  202.26 236.17 90 top
NOREF#1877  -  []  236.1 276.42 90 top
NOREF#1878  -  []  239.72 283.79 90 top
NOREF#1879  -  []  228.44 193.03 90 top
NOREF#1880  -  []  178.85 181.15 90 top
NOREF#1881  -  []  288.42 265.58 0 top
NOREF#1882  -  []  229.12 196.43 90 top
NOREF#1883  -  []  226.01 195.7 90 top
NOREF#1884  -  []  169.52 272.86 90 top
NOREF#1885  -  []  249.52 264.23 90 top
NOREF#1886  -  []  147.3 286.19 0 top
NOREF#1887  -  []  101.95 82.65 0 top
NOREF#1888  -  []  243.97 207.5 90 top
NOREF#1889  -  []  185.09 257.49 90 top
NOREF#1890  -  []  189.84 284.11 0 top
NOREF#1891  -  []  148.78 244.35 0 top
NOREF#1892  -  []  225.42 274.72 90 top
NOREF#1893  -  []  148.78 228.49 0 top
NOREF#1894  -  []  131.65 233.3 90 top
NOREF#1895  -  []  158.89 259.3 0 top
NOREF#1896  -  []  187 83.81 0 top
NOREF#1897  -  []  157.25 240.62 0 top
NOREF#1898  -  []  223.36 253.35 0 top
NOREF#1899  -  []  279.44 179.15 0 top
NOREF#1900  -  []  237.92 250.01 0 top
NOREF#1901  -  []  233.27 193.35 0 top
NOREF#1902  -  []  232.63 173.69 90 top
NOREF#1903  -  []  225.61 197.6 0 top
NOREF#1904  -  []  152.63 173.69 90 top
NOREF#1905  -  []  271.19 288.49 0 top
NOREF#1906  -  []  155.05 223.39 0 top
NOREF#1907  -  []  264.24 20.69 90 top
NOREF#1908  -  []  240.23 236.17 90 top
NOREF#1909  -  []  146.28 253.03 90 top
NOREF#1910  -  []  199.4 268.95 0 top
NOREF#1911  -  []  288.42 264.78 90 top
NOREF#1912  -  []  153.27 258.18 0 top
NOREF#1913  -  []  243.97 212 0 top
NOREF#1914  -  []  276.52 221.12 0 top
NOREF#1915  -  []  150.15 206.89 90 top
NOREF#1916  -  []  223.49 253.03 90 top
NOREF#1917  -  []  266.16 253.35 0 top
NOREF#1918  -  []  273.6 286.96 0 top
NOREF#1919  -  []  235.68 233.69 90 top
NOREF#1920  -  []  130.58 263.21 0 top
NOREF#1921  -  []  171.25 184.35 0 top
NOREF#1922  -  []  236.45 187.71 0 top
NOREF#1923  -  []  157.37 251.6 90 top
NOREF#1924  -  []  225.09 257.49 90 top
NOREF#1925  -  []  169.52 264.23 90 top
NOREF#1926  -  []  264.16 251.6 90 top
NOREF#1927  -  []  159.4 274.54 0 top
NOREF#1928  -  []  201.75 274.76 0 top
NOREF#1929  -  []  190.15 206.89 90 top
NOREF#1930  -  []  124.32 291.95 90 top
NOREF#1931  -  []  227.9 205.84 90 top
NOREF#1932  -  []  263.36 258.18 0 top
NOREF#1933  -  []  230.97 195.7 90 top
NOREF#1934  -  []  135.66 244.35 0 top
NOREF#1935  -  []  193.6 222.39 0 top
NOREF#1936  -  []  133.45 184.35 0 top
NOREF#1937  -  []  199.27 208.62 0 top
NOREF#1938  -  []  199.27 261.77 0 top
NOREF#1939  -  []  130.92 231.95 90 top
NOREF#1940  -  []  214.09 260.42 90 top
NOREF#1941  -  []  122.2 178.35 0 top
NOREF#1942  -  []  168.42 201.77 0 top
NOREF#1943  -  []  275.49 18.69 90 top
NOREF#1944  -  []  156.84 167.33 0 top
NOREF#1945  -  []  236.8 225.06 90 top
NOREF#1946  -  []  184.04 251.93 0 top
NOREF#1947  -  []  251.21 234.24 90 top
NOREF#1948  -  []  134.43 232.23 0 top
NOREF#1949  -  []  239.27 264.78 90 top
NOREF#1950  -  []  166.32 209.17 0 top
NOREF#1951  -  []  263.36 247.38 0 top
NOREF#1952  -  []  186.28 193.03 90 top
NOREF#1953  -  []  158.04 228.3 0 top
NOREF#1954  -  []  144.04 245.96 0 top
NOREF#1955  -  []  195.05 274.25 0 top
NOREF#1956  -  []  276.7 193.03 90 top
NOREF#1957  -  []  145.09 197.49 90 top
NOREF#1958  -  []  157.5 245.31 90 top
NOREF#1959  -  []  248.54 264.45 90 top
NOREF#1960  -  []  237.25 256.75 0 top
NOREF#1961  -  []  143.36 198.18 0 top
NOREF#1962  -  []  191.95 238.07 0 top
NOREF#1963  -  []  223.89 245.24 90 top
NOREF#1964  -  []  232.25 212.18 0 top
NOREF#1965  -  []  190.88 168.6 90 top
NOREF#1966  -  []  197.25 191.93 0 top
NOREF#1967  -  []  233.98 178.07 0 top
NOREF#1968  -  []  236.61 173.37 90 top
NOREF#1969  -  []  242.85 237.22 0 top
NOREF#1970  -  []  140.59 244.98 90 top
NOREF#1971  -  []  266.01 195.7 90 top
NOREF#1972  -  []  235.56 175.77 0 top
NOREF#1973  -  []  195.15 176.17 90 top
NOREF#1974  -  []  191.71 231.3 0 top
NOREF#1975  -  []  312.5 18.69 90 top
NOREF#1976  -  []  217.29 247.78 0 top
NOREF#1977  -  []  271.98 220.75 90 top
NOREF#1978  -  []  159.27 213.41 90 top
NOREF#1979  -  []  129.36 361.96 0 top
NOREF#1980  -  []  199.4 210.55 90 top
NOREF#1981  -  []  129.44 260.67 90 top
NOREF#1982  -  []  225.61 192.78 0 top
NOREF#1983  -  []  216.98 205.11 90 top
NOREF#1984  -  []  254.43 292.23 0 top
NOREF#1985  -  []  154.62 252.5 90 top
NOREF#1986  -  []  258.85 181.15 90 top
NOREF#1987  -  []  230.41 228.7 90 top
NOREF#1988  -  []  141.55 207.14 90 top
NOREF#1989  -  []  134.38 204.09 0 top
NOREF#1990  -  []  180.43 284.38 90 top
NOREF#1991  -  []  189.12 251.6 90 top
NOREF#1992  -  []  228.81 250.88 90 top
NOREF#1993  -  []  208.54 264.45 90 top
NOREF#1994  -  []  243.97 270.55 90 top
NOREF#1995  -  []  231.53 173.37 90 top
NOREF#1996  -  []  236.84 167.33 0 top
NOREF#1997  -  []  208.54 267.5 90 top
NOREF#1998  -  []  283.97 265.9 0 top
NOREF#1999  -  []  188.32 185.63 90 top
NOREF#2000  -  []  261.59 234.15 0 top
NOREF#2001  -  []  149.67 236.37 90 top
NOREF#2002  -  []  228.35 283.79 90 top
NOREF#2003  -  []  227.8 209.99 0 top
NOREF#2004  -  []  85.84 157.62 0 top
NOREF#2005  -  []  154.63 279.22 90 top
NOREF#2006  -  []  232.66 226.35 90 top
NOREF#2007  -  []  149.12 251.6 90 top
NOREF#2008  -  []  138.56 246.51 0 top
NOREF#2009  -  []  156.8 214.65 90 top
NOREF#2010  -  []  224.04 191.93 0 top
NOREF#2011  -  []  233.18 211.85 90 top
NOREF#2012  -  []  197.71 173.69 90 top
NOREF#2013  -  []  196.8 225.06 90 top
NOREF#2014  -  []  187.99 178.35 0 top
NOREF#2015  -  []  95.35 456.29 0 top
NOREF#2016  -  []  189.84 273.7 0 top
NOREF#2017  -  []  272.25 282.59 0 top
NOREF#2018  -  []  135.15 263.21 0 top
NOREF#2019  -  []  277.18 176.17 90 top
NOREF#2020  -  []  136.55 280.49 0 top
NOREF#2021  -  []  218.35 204.47 0 top
NOREF#2022  -  []  171.05 245.49 90 top
NOREF#2023  -  []  134.43 232.23 0 top
NOREF#2024  -  []  199.4 262.09 0 top
NOREF#2025  -  []  99.98 392.33 90 top
NOREF#2026  -  []  203.84 273.41 90 top
NOREF#2027  -  []  239.4 270.55 90 top
NOREF#2028  -  []  233.18 222.26 90 top
NOREF#2029  -  []  187.43 284.11 0 top
NOREF#2030  -  []  190.56 252.78 0 top
NOREF#2031  -  []  159.65 272.56 0 top
NOREF#2032  -  []  156.79 231.3 0 top
NOREF#2033  -  []  283.84 268.62 0 top
NOREF#2034  -  []  156.57 185.63 90 top
NOREF#2035  -  []  185.41 213.02 90 top
NOREF#2036  -  []  279.4 213.09 90 top
NOREF#2037  -  []  241.75 209.17 0 top
NOREF#2038  -  []  234.33 264.33 90 top
NOREF#2039  -  []  171.25 244.35 0 top
NOREF#2040  -  []  140.83 263.76 90 top
NOREF#2041  -  []  257.25 236.5 90 top
NOREF#2042  -  []  165.38 226.23 0 top
NOREF#2043  -  []  156.61 233.37 90 top
NOREF#2044  -  []  279.27 208.62 0 top
NOREF#2045  -  []  288.42 205.58 0 top
NOREF#2046  -  []  185.41 273.02 90 top
NOREF#2047  -  []  156.7 197.85 90 top
NOREF#2048  -  []  250.89 269.17 0 top
NOREF#2049  -  []  197.04 244.35 0 top
NOREF#2050  -  []  187.77 197.6 0 top
NOREF#2051  -  []  238.91 172.21 90 top
NOREF#2052  -  []  124.61 294.24 90 top
NOREF#2053  -  []  131.26 184.35 0 top
NOREF#2054  -  []  181.6 234.15 0 top
NOREF#2055  -  []  140.95 264.09 90 top
NOREF#2056  -  []  173.36 201.22 0 top
NOREF#2057  -  []  229.12 180.3 90 top
NOREF#2058  -  []  230.97 179.57 90 top
NOREF#2059  -  []  106.68 128.02 90 top
NOREF#2060  -  []  159.27 207.82 90 top
NOREF#2061  -  []  191.71 171.3 0 top
NOREF#2062  -  []  186.16 198.18 0 top
NOREF#2063  -  []  150.77 219.22 90 top
NOREF#2064  -  []  266.16 226.14 90 top
NOREF#2065  -  []  228.44 253.03 90 top
NOREF#2066  -  []  159.4 264.45 90 top
NOREF#2067  -  []  290.89 202.32 0 top
NOREF#2068  -  []  259.73 238.35 0 top
NOREF#2069  -  []  143.61 396.29 0 top
NOREF#2070  -  []  281.44 244.35 0 top
NOREF#2071  -  []  254.43 292.23 0 top
NOREF#2072  -  []  232.25 218.02 0 top
NOREF#2073  -  []  268.32 245.63 90 top
NOREF#2074  -  []  208.42 205.58 0 top
NOREF#2075  -  []  258.35 271.84 0 top
NOREF#2076  -  []  272.63 233.69 90 top
NOREF#2077  -  []  162.44 232.28 0 top
NOREF#2078  -  []  253.65 179.15 0 top
NOREF#2079  -  []  209.49 280.89 0 top
NOREF#2080  -  []  272.51 235.77 0 top
NOREF#2081  -  []  231.73 232.54 0 top
NOREF#2082  -  []  192.13 274.25 0 top
NOREF#2083  -  []  281.41 167.9 90 top
NOREF#2084  -  []  235.26 83.81 0 top
NOREF#2085  -  []  252.55 224.49 0 top
NOREF#2086  -  []  169.49 280.89 0 top
NOREF#2087  -  []  147.8 269.99 0 top
NOREF#2088  -  []  153.18 217.69 90 top
NOREF#2089  -  []  256.38 204.09 90 top
NOREF#2090  -  []  143.49 247.06 90 top
NOREF#2091  -  []  136.55 194.49 90 top
NOREF#2092  -  []  136.63 292.23 0 top
NOREF#2093  -  []  171.22 294.89 90 top
NOREF#2094  -  []  174.09 207.27 90 top
NOREF#2095  -  []  174.38 264.09 0 top
NOREF#2096  -  []  231.91 196.43 90 top
NOREF#2097  -  []  203.84 271.67 0 top
NOREF#2098  -  []  268.32 182.05 0 top
NOREF#2099  -  []  239.4 207.5 90 top
NOREF#2100  -  []  124.61 234.24 90 top
NOREF#2101  -  []  236.57 185.63 90 top
NOREF#2102  -  []  186.16 286.14 90 top
NOREF#2103  -  []  267.8 265.39 90 top
NOREF#2104  -  []  157.74 166.36 90 top
NOREF#2105  -  []  173.34 17.15 90 top
NOREF#2106  -  []  274.39 282.02 90 top
NOREF#2107  -  []  199.27 271.67 0 top
NOREF#2108  -  []  151.18 179.15 0 top
NOREF#2109  -  []  186.16 212.17 90 top
NOREF#2110  -  []  275.96 168.6 90 top
NOREF#2111  -  []  247.95 226.12 90 top
NOREF#2112  -  []  187.8 264.99 90 top
NOREF#2113  -  []  211.05 232.28 90 top
NOREF#2114  -  []  237.74 166.36 90 top
NOREF#2115  -  []  208.54 202.09 0 top
NOREF#2116  -  []  259.08 203.76 0 top
NOREF#2117  -  []  276.1 276.42 90 top
NOREF#2118  -  []  152.25 222.59 90 top
NOREF#2119  -  []  259.4 458.49 0 top
NOREF#2120  -  []  233.94 191.93 0 top
NOREF#2121  -  []  224.16 185.63 90 top
NOREF#2122  -  []  243.84 267.82 90 top
NOREF#2123  -  []  208.54 200.64 90 top
NOREF#2124  -  []  239.27 268.62 0 top
NOREF#2125  -  []  202.57 291.95 0 top
NOREF#2126  -  []  279.27 273.41 90 top
NOREF#2127  -  []  156.61 173.37 90 top
NOREF#2128  -  []  232.72 257.6 0 top
NOREF#2129  -  []  104.35 456.29 0 top
NOREF#2130  -  []  139.55 180.49 90 top
NOREF#2131  -  []  193.18 217.69 90 top
NOREF#2132  -  []  279.27 210.87 90 top
NOREF#2133  -  []  135.15 260.67 90 top
NOREF#2134  -  []  195.17 212.18 0 top
NOREF#2135  -  []  178.35 209.04 0 top
NOREF#2136  -  []  272.87 188.11 90 top
NOREF#2137  -  []  131.05 232.28 90 top
NOREF#2138  -  []  151.11 193.35 0 top
NOREF#2139  -  []  232.87 188.11 90 top
NOREF#2140  -  []  283.53 457.2 0 top
NOREF#2141  -  []  266.96 256.43 90 top
NOREF#2142  -  []  139.08 205.79 0 top
NOREF#2143  -  []  167.74 456.29 0 top
NOREF#2144  -  []  213.45 184.35 0 top
NOREF#2145  -  []  188.32 198.18 0 top
NOREF#2146  -  []  178.35 211.84 0 top
NOREF#2147  -  []  161.75 266.13 0 top
NOREF#2148  -  []  276.8 220.49 90 top
NOREF#2149  -  []  177.29 187.78 0 top
NOREF#2150  -  []  268.81 190.88 90 top
NOREF#2151  -  []  163.84 265.58 0 top
NOREF#2152  -  []  141.85 232.5 0 top
NOREF#2153  -  []  155.49 228.7 90 top
NOREF#2154  -  []  248.42 260.97 90 top
NOREF#2155  -  []  151.71 171.3 0 top
NOREF#2156  -  []  276.61 233.37 90 top
NOREF#2157  -  []  279.24 244.35 0 top
NOREF#2158  -  []  226.43 282.49 90 top
NOREF#2159  -  []  326.72 389.27 90 top
NOREF#2160  -  []  189.24 185.31 90 top
NOREF#2161  -  []  248.42 207.82 90 top
NOREF#2162  -  []  163.97 274.54 0 top
NOREF#2163  -  []  171.05 292.28 90 top
NOREF#2164  -  []  276.52 285.69 0 top
NOREF#2165  -  []  153.95 191.93 0 top
NOREF#2166  -  []  289.52 267.27 90 top
NOREF#2167  -  []  160.23 236.17 90 top
NOREF#2168  -  []  275.17 276.75 0 top
NOREF#2169  -  []  62.86 375.04 0 top
NOREF#2170  -  []  192.25 272.17 0 top
NOREF#2171  -  []  250.89 206.13 0 top
NOREF#2172  -  []  249.52 210.32 90 top
NOREF#2173  -  []  148.81 195.7 90 top
NOREF#2174  -  []  233.18 217.69 90 top
NOREF#2175  -  []  152.25 212.18 0 top
NOREF#2176  -  []  239.27 213.41 90 top
NOREF#2177  -  []  216 456.29 90 top
NOREF#2178  -  []  268.35 217.95 90 top
NOREF#2179  -  []  235.17 221.32 0 top
NOREF#2180  -  []  248.54 204.45 90 top
NOREF#2181  -  []  270.88 168.6 90 top
NOREF#2182  -  []  209.55 237.49 0 top
NOREF#2183  -  []  187.3 280.35 0 top
NOREF#2184  -  []  218.85 181.15 90 top
NOREF#2185  -  []  187.77 252.78 0 top
NOREF#2186  -  []  218.35 271.84 0 top
NOREF#2187  -  []  135.66 184.35 0 top
NOREF#2188  -  []  150.56 192.78 0 top
NOREF#2189  -  []  228.44 257.85 90 top
NOREF#2190  -  []  154.07 196.43 90 top
NOREF#2191  -  []  156.7 181.72 90 top
NOREF#2192  -  []  163.84 213.41 90 top
NOREF#2193  -  []  237.37 196.43 90 top
NOREF#2194  -  []  254.33 389.27 90 top
NOREF#2195  -  []  159.27 264.78 90 top
NOREF#2196  -  []  252.64 264.47 0 top
NOREF#2197  -  []  233.94 196.75 0 top
NOREF#2198  -  []  180.83 263.76 90 top
NOREF#2199  -  []  191.19 218.07 0 top
NOREF#2200  -  []  196.52 281.12 0 top
NOREF#2201  -  []  275.68 233.69 0 top
NOREF#2202  -  []  212.64 204.47 0 top
NOREF#2203  -  []  152.25 282.59 90 top
NOREF#2204  -  []  307.65 17.78 0 top
NOREF#2205  -  []  128.48 456.29 0 top
NOREF#2206  -  []  236.02 241.47 0 top
NOREF#2207  -  []  276.8 274.65 90 top
NOREF#2208  -  []  136.38 204.09 90 top
NOREF#2209  -  []  157.28 264.37 0 top
NOREF#2210  -  []  288.42 200.97 90 top
NOREF#2211  -  []  151.46 167 0 top
NOREF#2212  -  []  260.43 284.38 90 top
NOREF#2213  -  []  178.85 241.15 90 top
NOREF#2214  -  []  148.78 184.35 0 top
NOREF#2215  -  []  236.57 258.18 0 top
NOREF#2216  -  []  283.84 274.21 0 top
NOREF#2217  -  []  279.4 205.9 0 top
NOREF#2218  -  []  268.35 223.79 90 top
NOREF#2219  -  []  271.91 256.43 90 top
NOREF#2220  -  []  196.52 216.55 0 top
NOREF#2221  -  []  239.22 250.88 90 top
NOREF#2222  -  []  233.83 232.21 90 top
NOREF#2223  -  []  199.22 179.57 90 top
NOREF#2224  -  []  151.73 172.54 0 top
NOREF#2225  -  []  168.54 262.09 0 top
NOREF#2226  -  []  261.55 267.14 90 top
NOREF#2227  -  []  188.35 217.95 90 top
NOREF#2228  -  []  276.02 197.6 0 top
NOREF#2229  -  []  159.4 202.09 0 top
NOREF#2230  -  []  294.09 200.42 90 top
NOREF#2231  -  []  150.15 266.89 90 top
NOREF#2232  -  []  235.49 228.7 90 top
NOREF#2233  -  []  146.16 198.18 0 top
NOREF#2234  -  []  208.42 267.82 90 top
NOREF#2235  -  []  276.57 198.18 0 top
NOREF#2236  -  []  157.25 191.93 0 top
NOREF#2237  -  []  270.56 192.78 0 top
NOREF#2238  -  []  146.7 223.05 90 top
NOREF#2239  -  []  236.8 220.49 90 top
NOREF#2240  -  []  240.13 456.29 0 top
NOREF#2241  -  []  191.95 178.07 0 top
NOREF#2242  -  []  188.78 282.65 0 top
NOREF#2243  -  []  254.07 210.89 90 top
NOREF#2244  -  []  164.61 294.24 90 top
NOREF#2245  -  []  189.67 190.01 0 top
NOREF#2246  -  []  239.24 244.35 0 top
NOREF#2247  -  []  241.75 212.22 0 top
NOREF#2248  -  []  157.25 251.93 0 top
NOREF#2249  -  []  268.32 185.63 0 top
NOREF#2250  -  []  151.79 196.75 0 top
NOREF#2251  -  []  196.5 392.33 90 top
NOREF#2252  -  []  163.97 210.55 90 top
NOREF#2253  -  []  254 14.59 90 top
NOREF#2254  -  []  205.38 286.23 0 top
NOREF#2255  -  []  235.58 262.67 90 top
NOREF#2256  -  []  196.57 193.35 0 top
NOREF#2257  -  []  193.83 232.21 90 top
NOREF#2258  -  []  195.17 272.17 0 top
NOREF#2259  -  []  196.8 220.49 90 top
NOREF#2260  -  []  189.84 273.7 90 top
NOREF#2261  -  []  177.25 236.5 90 top
NOREF#2262  -  []  163.97 214.54 0 top
NOREF#2263  -  []  299.62 18.69 90 top
NOREF#2264  -  []  163.97 267.5 90 top
NOREF#2265  -  []  281.75 202.32 0 top
NOREF#2266  -  []  213.78 207.01 0 top
NOREF#2267  -  []  273.27 253.35 0 top
NOREF#2268  -  []  159.4 207.5 90 top
NOREF#2269  -  []  88.14 134.87 0 top
NOREF#2270  -  []  204.61 234.89 90 top
NOREF#2271  -  []  279.27 200.97 90 top
NOREF#2272  -  []  93.68 156.59 0 top
NOREF#2273  -  []  235.17 212.18 0 top
NOREF#2274  -  []  185.61 252.78 0 top
NOREF#2275  -  []  163.97 262.09 0 top
NOREF#2276  -  []  271.24 257.85 90 top
NOREF#2277  -  []  144.04 185.96 0 top
NOREF#2278  -  []  161.12 188.11 90 top
NOREF#2279  -  []  159.4 204.45 90 top
NOREF#2280  -  []  210.92 231.95 90 top
NOREF#2281  -  []  199.4 272 0 top
NOREF#2282  -  []  187.43 284.11 90 top
NOREF#2283  -  []  88.44 107.76 0 top
NOREF#2284  -  []  266.83 191.93 0 top
NOREF#2285  -  []  199.72 219.22 90 top
NOREF#2286  -  []  255.84 202.57 90 top
NOREF#2287  -  []  283.52 83.81 0 top
NOREF#2288  -  []  276.1 216.42 90 top
NOREF#2289  -  []  271.91 196.43 90 top
NOREF#2290  -  []  167.74 396.29 0 top
NOREF#2291  -  []  278.11 232.1 0 top
NOREF#2292  -  []  266.01 190.88 90 top
NOREF#2293  -  []  188.99 191.93 0 top
NOREF#2294  -  []  259.08 265.79 0 top
NOREF#2295  -  []  219.55 234.49 0 top
NOREF#2296  -  []  195.96 228.6 90 top
NOREF#2297  -  []  150.56 252.5 0 top
NOREF#2298  -  []  159.24 244.35 0 top
NOREF#2299  -  []  188.44 257.85 90 top
NOREF#2300  -  []  206.32 272.22 0 top
NOREF#2301  -  []  214.51 263.76 0 top
NOREF#2302  -  []  286.32 262.32 0 top
NOREF#2303  -  []  95.35 452.29 90 top
NOREF#2304  -  []  162.85 297.22 0 top
NOREF#2305  -  []  147.51 252.5 90 top
NOREF#2306  -  []  124.44 232.28 90 top
NOREF#2307  -  []  247.95 286.12 90 top
NOREF#2308  -  []  236.8 214.65 90 top
NOREF#2309  -  []  205.04 293.3 90 top
NOREF#2310  -  []  148.24 392.33 90 top
NOREF#2311  -  []  194.39 282.02 90 top
NOREF#2312  -  []  231.79 196.75 0 top
NOREF#2313  -  []  130.58 263.21 90 top
NOREF#2314  -  []  253.65 239.15 0 top
NOREF#2315  -  []  89.76 144.42 90 top
NOREF#2316  -  []  239.22 255.7 90 top
NOREF#2317  -  []  259.08 261.22 0 top
NOREF#2318  -  []  288.39 452.29 90 top
NOREF#2319  -  []  190.77 283.79 90 top
NOREF#2320  -  []  178.95 201.55 0 top
NOREF#2321  -  []  233.27 198.18 0 top
NOREF#2322  -  []  193.6 282.39 0 top
NOREF#2323  -  []  231.91 251.6 90 top
NOREF#2324  -  []  159.27 200.97 90 top
NOREF#2325  -  []  163.97 212 0 top
NOREF#2326  -  []  229.84 224.11 90 top
NOREF#2327  -  []  152.25 278.02 0 top
NOREF#2328  -  []  259.08 205.79 0 top
NOREF#2329  -  []  246.32 214.76 0 top
NOREF#2330  -  []  199.4 214.54 0 top
NOREF#2331  -  []  174.51 203.76 0 top
NOREF#2332  -  []  192.87 248.11 90 top
NOREF#2333  -  []  226.28 257.85 90 top
NOREF#2334  -  []  230.56 192.78 0 top
NOREF#2335  -  []  178.95 266.12 0 top
NOREF#2336  -  []  208.45 235.2 0 top
NOREF#2337  -  []  190.48 235.77 0 top
NOREF#2338  -  []  209.55 237.49 0 top
NOREF#2339  -  []  271.46 167 0 top
NOREF#2340  -  []  143.89 185.24 90 top
NOREF#2341  -  []  153.76 195.7 90 top
NOREF#2342  -  []  218.95 261.55 0 top
NOREF#2343  -  []  268.78 184.35 0 top
NOREF#2344  -  []  239.27 208.62 0 top
NOREF#2345  -  []  182.81 186.81 0 top
NOREF#2346  -  []  178.97 271.91 90 top
NOREF#2347  -  []  181.85 232.5 0 top
NOREF#2348  -  []  283.97 262.09 0 top
NOREF#2349  -  []  182.87 273.02 0 top
NOREF#2350  -  []  164.04 237.5 90 top
NOREF#2351  -  []  86.61 132.84 0 top
NOREF#2352  -  []  152.63 233.69 90 top
NOREF#2353  -  []  259.73 178.35 0 top
NOREF#2354  -  []  249.52 212.86 90 top
NOREF#2355  -  []  221.59 248.12 0 top
NOREF#2356  -  []  243.84 271.67 0 top
NOREF#2357  -  []  230.77 279.22 90 top
NOREF#2358  -  []  193.56 173.37 90 top
NOREF#2359  -  []  139.72 273.6 90 top
NOREF#2360  -  []  189.84 213.7 0 top
NOREF#2361  -  []  163.84 271.67 0 top
NOREF#2362  -  []  151.46 227 0 top
NOREF#2363  -  []  142.81 197.6 0 top
NOREF#2364  -  []  275.58 262.67 90 top
NOREF#2365  -  []  228.78 184.35 0 top
NOREF#2366  -  []  122.85 237.22 0 top
NOREF#2367  -  []  189.12 191.6 90 top
NOREF#2368  -  []  190.6 173.69 0 top
NOREF#2369  -  []  214.09 200.42 90 top
NOREF#2370  -  []  170.02 214.45 0 top
NOREF#2371  -  []  203.84 211.67 0 top
NOREF#2372  -  []  154.07 251.6 90 top
NOREF#2373  -  []  258.83 292.23 0 top
NOREF#2374  -  []  275.58 202.67 90 top
NOREF#2375  -  []  233.94 256.75 0 top
NOREF#2376  -  []  209.55 237.49 0 top
NOREF#2377  -  []  161.84 235.2 0 top
